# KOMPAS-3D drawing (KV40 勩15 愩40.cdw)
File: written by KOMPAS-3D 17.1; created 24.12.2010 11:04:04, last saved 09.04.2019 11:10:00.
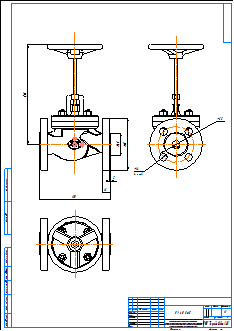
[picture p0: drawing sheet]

Title block, sheet 1: name: KV 40 Ду15; material: Внимание! Данный продукт является объектом авторского права ООО «Торговый Дом АДЛ». / Запрещается изменение, копирование, распространение / (в том числе путем копирования на другие сайты и ресурсы в Интернете) / или любое иное использование информации и объектов без предварительного / согласия правообладателя (ООО «Торговый Дом АДЛ»); scale: 1:1; sheets: 1; organisation: ООО "Торговый дом АДЛ"; sheet format: A2; stored path: \\adlc.lan\data\АДЛ_ПКД\3D-модели\ADL production\Вентили ГРАНВЕНТ\KV40\KOMPAS 2D\KV 40 Ду15.cdw

Views: Спереди 1, Проекционный вид 2, Вид 5
Dimensions and other numbers on the sheet: 45; 95; 16; 2; 130; 180; 65; 14; 4 отв.; 1:1; 1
